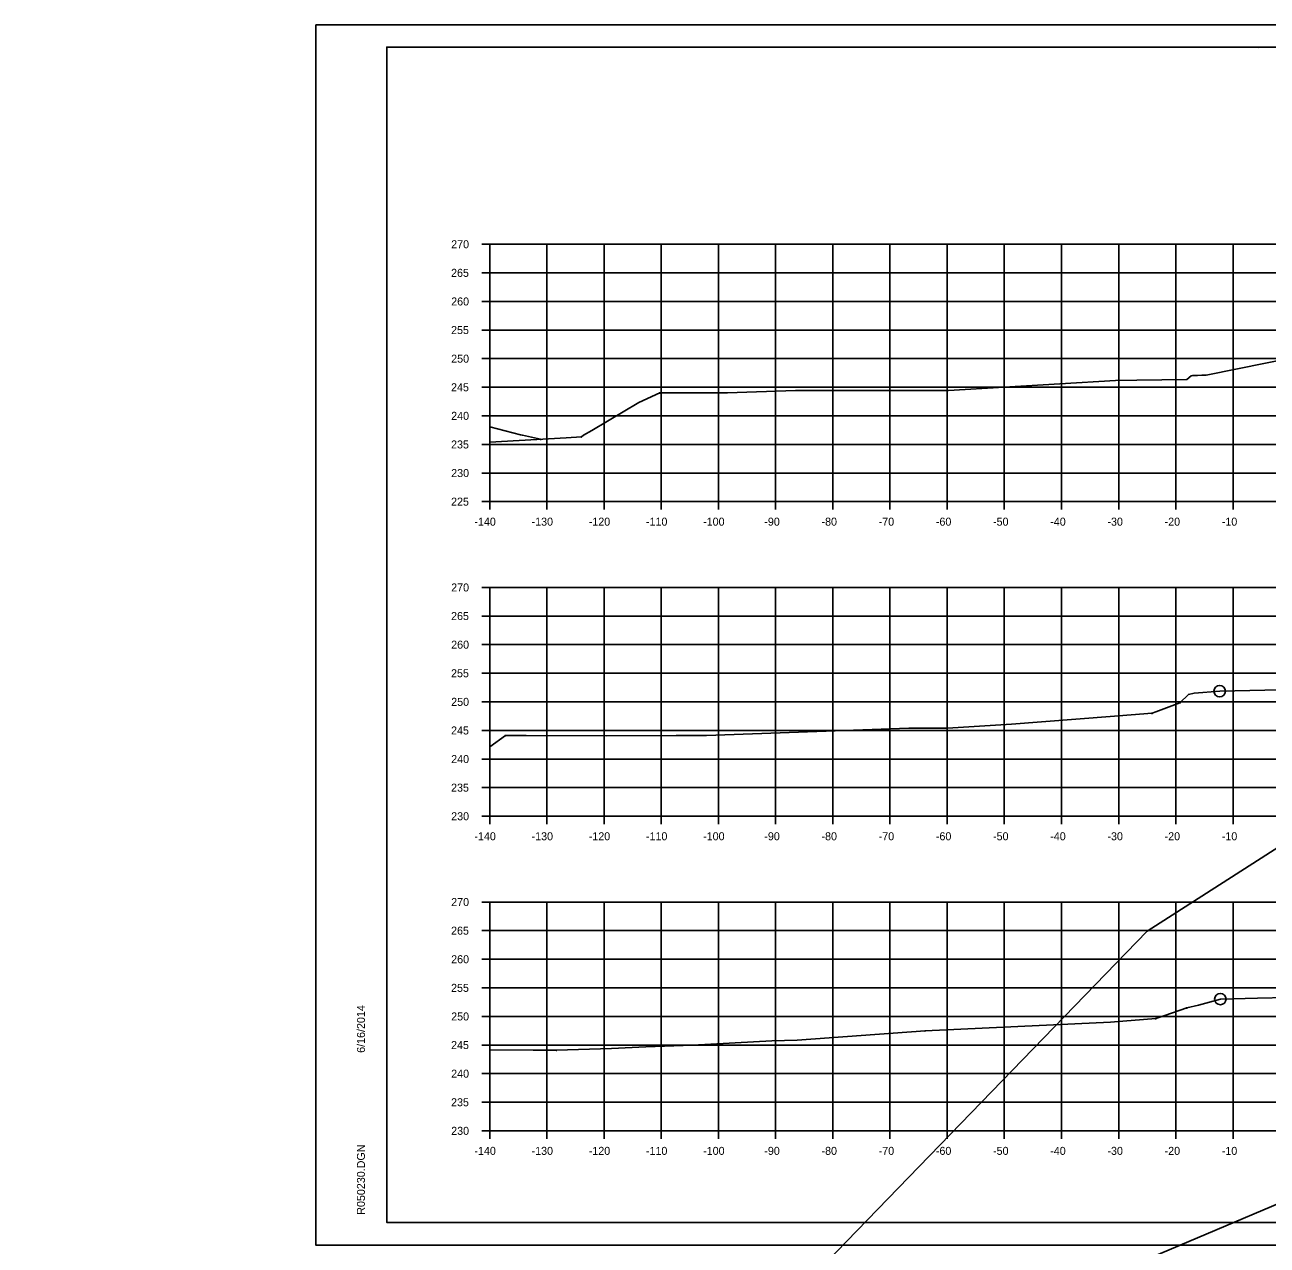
# Model space of a CAD drawing. Extents: x 1300404 to 1323571, y 234004 to 252077.
# Drawn here: x 1315496 to 1315713.2, y 240208.4 to 240421.8 of the extents above; entities that cross this region are included whole.
import ezdxf

# ---------------------------------------------------------------- set-up
doc = ezdxf.new("R2010")
doc.units = 0
for name, color, linetype in [('Default', 7, 'Continuous'), ('R_Axis', 7, 'Continuous'), ('R_Axis Annot', 7, 'Continuous'), ('R_Border', 7, 'Continuous'), ('R_Draft', 7, 'Continuous'), ('R_Exist Surface', 7, 'Continuous'), ('R_Fin Surface', 7, 'Continuous'), ('R_Floodway', 7, 'Continuous'), ('R_Flooplain', 7, 'Continuous'), ('R_Grid', 7, 'Continuous'), ('R_No Plot', 7, 'Continuous')]:
    doc.layers.add(name, color=color, linetype=linetype)

msp = doc.modelspace()

# ---------------------------------------------------------------- linework, layer by layer
at = {"layer": 'Default'}
for p, q in [((1315559.28, 240417.86), (1315875.46, 240417.86)), ((1315559.28, 240212.4), (1315559.28, 240417.86)), ((1315875.46, 240212.4), (1315559.28, 240212.4))]:
    msp.add_line(p, q, dxfattribs=at)
at = {"layer": 'R_Axis'}
for p, q in [((1315575.88, 240383.4), (1315577.28, 240383.4)), ((1315577.28, 240338.4), (1315577.28, 240383.4)), ((1315575.88, 240378.4), (1315577.28, 240378.4)), ((1315575.88, 240373.4), (1315577.28, 240373.4)), ((1315575.88, 240368.4), (1315577.28, 240368.4)), ((1315575.88, 240363.4), (1315577.28, 240363.4)), ((1315575.88, 240358.4), (1315577.28, 240358.4)), ((1315575.88, 240353.4), (1315577.28, 240353.4)), ((1315575.88, 240348.4), (1315577.28, 240348.4)), ((1315575.88, 240343.4), (1315577.28, 240343.4)), ((1315575.88, 240338.4), (1315577.28, 240338.4)), ((1315577.28, 240338.4), (1315857.28, 240338.4)), ((1315577.28, 240337), (1315577.28, 240338.4)), ((1315587.28, 240337), (1315587.28, 240338.4)), ((1315597.28, 240337), (1315597.28, 240338.4)), ((1315607.28, 240337), (1315607.28, 240338.4)), ((1315617.28, 240337), (1315617.28, 240338.4)), ((1315627.28, 240337), (1315627.28, 240338.4)), ((1315637.28, 240337), (1315637.28, 240338.4)), ((1315647.28, 240337), (1315647.28, 240338.4)), ((1315657.28, 240337), (1315657.28, 240338.4)), ((1315667.28, 240337), (1315667.28, 240338.4)), ((1315677.28, 240337), (1315677.28, 240338.4)), ((1315687.28, 240337), (1315687.28, 240338.4)), ((1315697.28, 240337), (1315697.28, 240338.4)), ((1315707.28, 240337), (1315707.28, 240338.4)), ((1315575.88, 240323.4), (1315577.28, 240323.4)), ((1315577.28, 240283.4), (1315577.28, 240323.4)), ((1315575.88, 240318.4), (1315577.28, 240318.4)), ((1315575.88, 240313.4), (1315577.28, 240313.4)), ((1315575.88, 240308.4), (1315577.28, 240308.4)), ((1315575.88, 240303.4), (1315577.28, 240303.4)), ((1315575.88, 240298.4), (1315577.28, 240298.4)), ((1315575.88, 240293.4), (1315577.28, 240293.4)), ((1315575.88, 240288.4), (1315577.28, 240288.4)), ((1315575.88, 240283.4), (1315577.28, 240283.4)), ((1315577.28, 240283.4), (1315857.28, 240283.4)), ((1315577.28, 240282), (1315577.28, 240283.4)), ((1315587.28, 240282), (1315587.28, 240283.4)), ((1315597.28, 240282), (1315597.28, 240283.4)), ((1315607.28, 240282), (1315607.28, 240283.4)), ((1315617.28, 240282), (1315617.28, 240283.4)), ((1315627.28, 240282), (1315627.28, 240283.4)), ((1315637.28, 240282), (1315637.28, 240283.4)), ((1315647.28, 240282), (1315647.28, 240283.4)), ((1315657.28, 240282), (1315657.28, 240283.4)), ((1315667.28, 240282), (1315667.28, 240283.4)), ((1315677.28, 240282), (1315677.28, 240283.4)), ((1315687.28, 240282), (1315687.28, 240283.4)), ((1315697.28, 240282), (1315697.28, 240283.4)), ((1315707.28, 240282), (1315707.28, 240283.4)), ((1315575.88, 240268.4), (1315577.28, 240268.4)), ((1315577.28, 240228.4), (1315577.28, 240268.4)), ((1315575.88, 240263.4), (1315577.28, 240263.4)), ((1315575.88, 240258.4), (1315577.28, 240258.4)), ((1315575.88, 240253.4), (1315577.28, 240253.4)), ((1315575.88, 240248.4), (1315577.28, 240248.4)), ((1315575.88, 240243.4), (1315577.28, 240243.4)), ((1315575.88, 240238.4), (1315577.28, 240238.4)), ((1315575.88, 240233.4), (1315577.28, 240233.4)), ((1315575.88, 240228.4), (1315577.28, 240228.4)), ((1315577.28, 240228.4), (1315857.28, 240228.4)), ((1315577.28, 240227), (1315577.28, 240228.4)), ((1315587.28, 240227), (1315587.28, 240228.4)), ((1315597.28, 240227), (1315597.28, 240228.4)), ((1315607.28, 240227), (1315607.28, 240228.4)), ((1315617.28, 240227), (1315617.28, 240228.4)), ((1315627.28, 240227), (1315627.28, 240228.4)), ((1315637.28, 240227), (1315637.28, 240228.4)), ((1315647.28, 240227), (1315647.28, 240228.4)), ((1315657.28, 240227), (1315657.28, 240228.4)), ((1315667.28, 240227), (1315667.28, 240228.4)), ((1315677.28, 240227), (1315677.28, 240228.4)), ((1315687.28, 240227), (1315687.28, 240228.4)), ((1315697.28, 240227), (1315697.28, 240228.4)), ((1315707.28, 240227), (1315707.28, 240228.4))]:
    msp.add_line(p, q, dxfattribs=at)
at = {"layer": 'R_Border'}
for p, q in [((1315711.8, 240417.6), (1315711.8, 240417.6)), ((1315711.8, 240417.6), (1315711.8, 240417.6)), ((1315559.28, 240212.4), (1315559.28, 240212.4))]:
    msp.add_line(p, q, dxfattribs=at)
at = {"layer": 'R_Draft'}
for points in [[(1315699.17, 240359.83), (1315699.22, 240359.73), (1315699.12, 240359.73)], [(1315607.02, 240357.47), (1315607.07, 240357.37), (1315606.97, 240357.37)], [(1315586.19, 240349.35), (1315586.24, 240349.25), (1315586.14, 240349.25)], [(1315586.19, 240349.35), (1315586.24, 240349.25), (1315586.14, 240349.25)], [(1315593.31, 240349.78), (1315593.36, 240349.68), (1315593.26, 240349.68)], [(1315697.99, 240303.3), (1315698.04, 240303.2), (1315697.94, 240303.2)], [(1315693.11, 240301.45), (1315693.16, 240301.35), (1315693.06, 240301.35)], [(1315580.05, 240297.58), (1315580.1, 240297.48), (1315580, 240297.48)], [(1315699.19, 240249.94), (1315699.24, 240249.84), (1315699.14, 240249.84)], [(1315693.75, 240248.07), (1315693.8, 240247.97), (1315693.7, 240247.97)], [(1315653.41, 240245.94), (1315653.46, 240245.84), (1315653.36, 240245.84)], [(1315588.95, 240242.57), (1315589, 240242.47), (1315588.9, 240242.47)]]:
    msp.add_lwpolyline(points, close=True, dxfattribs=at)
at = {"layer": 'R_Exist Surface'}
for points in [[(1315577.28, 240348.79), (1315590.67, 240349.54), (1315593.31, 240349.73), (1315593.67, 240350.01), (1315595.17, 240350.84), (1315603.37, 240355.73), (1315607.02, 240357.42), (1315618.86, 240357.42), (1315630.79, 240357.85), (1315646.67, 240357.82), (1315657.52, 240357.81), (1315686.75, 240359.59), (1315690.45, 240359.66), (1315699.17, 240359.78), (1315699.97, 240360.4), (1315700.02, 240360.4), (1315700.22, 240360.46), (1315700.27, 240360.46), (1315700.32, 240360.46), (1315700.46, 240360.46), (1315700.87, 240360.47), (1315701, 240360.47), (1315701.08, 240360.47), (1315701.83, 240360.5), (1315702.14, 240360.51), (1315702.58, 240360.52), (1315718.41, 240363.74)], [(1315577.28, 240295.56), (1315580.05, 240297.53), (1315581.67, 240297.52), (1315583.69, 240297.51), (1315597.75, 240297.46), (1315609.89, 240297.52), (1315615.18, 240297.52), (1315650.59, 240298.81), (1315654.59, 240298.8), (1315657.33, 240298.79), (1315668.52, 240299.48), (1315685.78, 240300.82), (1315693.11, 240301.4), (1315693.79, 240301.64), (1315697.99, 240303.25), (1315699.47, 240304.69), (1315700.48, 240304.94), (1315704.94, 240305.27), (1315712.85, 240305.44), (1315714.85, 240305.52)], [(1315577.28, 240242.56), (1315584.88, 240242.52), (1315588.95, 240242.52), (1315598.57, 240242.8), (1315604.59, 240243.09), (1315612.72, 240243.38), (1315626.65, 240244.12), (1315631.08, 240244.28), (1315653.41, 240245.89), (1315685.82, 240247.4), (1315693.75, 240248.02), (1315695.34, 240248.59), (1315699.19, 240249.89), (1315701.22, 240250.38), (1315705.06, 240251.44), (1315711.57, 240251.59), (1315716.75, 240251.7)]]:
    msp.add_lwpolyline(points, dxfattribs=at)
at = {"layer": 'R_Fin Surface'}
msp.add_lwpolyline([(1315577.28, 240351.45), (1315582.65, 240350.07), (1315582.97, 240350), (1315583.02, 240350), (1315586.19, 240349.3)], dxfattribs=at)
at = {"layer": 'R_Floodway'}
msp.add_lwpolyline([(1316837.8, 240552.77), (1316620.61, 240466.93), (1316398.83, 240386.16), (1316131.18, 240356.09), (1315994.58, 240333.94), (1315688.1, 240204.21), (1315576.62, 240103.36), (1315282.23, 239827.84), (1314935.72, 239477.52)], dxfattribs=at)
at = {"layer": 'R_Flooplain'}
for p, q in [((1315692.25, 240263.28), (1316007.17, 240465.17)), ((1314740.93, 239282.88), (1315692.25, 240263.28))]:
    msp.add_line(p, q, dxfattribs=at)
at = {"layer": 'R_Grid'}
for p, q in [((1315577.28, 240383.4), (1315857.28, 240383.4)), ((1315577.28, 240338.4), (1315577.28, 240383.4)), ((1315587.28, 240338.4), (1315587.28, 240383.4)), ((1315597.28, 240338.4), (1315597.28, 240383.4)), ((1315607.28, 240338.4), (1315607.28, 240383.4)), ((1315617.28, 240338.4), (1315617.28, 240383.4)), ((1315627.28, 240338.4), (1315627.28, 240383.4)), ((1315637.28, 240338.4), (1315637.28, 240383.4)), ((1315647.28, 240338.4), (1315647.28, 240383.4)), ((1315657.28, 240338.4), (1315657.28, 240383.4)), ((1315667.28, 240338.4), (1315667.28, 240383.4)), ((1315677.28, 240338.4), (1315677.28, 240383.4)), ((1315687.28, 240338.4), (1315687.28, 240383.4)), ((1315697.28, 240338.4), (1315697.28, 240383.4)), ((1315707.28, 240338.4), (1315707.28, 240383.4)), ((1315577.28, 240378.4), (1315857.28, 240378.4)), ((1315577.28, 240373.4), (1315857.28, 240373.4)), ((1315577.28, 240368.4), (1315857.28, 240368.4)), ((1315577.28, 240363.4), (1315857.28, 240363.4)), ((1315577.28, 240358.4), (1315857.28, 240358.4)), ((1315577.28, 240353.4), (1315857.28, 240353.4)), ((1315577.28, 240348.4), (1315857.28, 240348.4)), ((1315577.28, 240343.4), (1315857.28, 240343.4)), ((1315577.28, 240338.4), (1315857.28, 240338.4)), ((1315577.28, 240323.4), (1315857.28, 240323.4)), ((1315577.28, 240283.4), (1315577.28, 240323.4)), ((1315587.28, 240283.4), (1315587.28, 240323.4)), ((1315597.28, 240283.4), (1315597.28, 240323.4)), ((1315607.28, 240283.4), (1315607.28, 240323.4)), ((1315617.28, 240283.4), (1315617.28, 240323.4)), ((1315627.28, 240283.4), (1315627.28, 240323.4)), ((1315637.28, 240283.4), (1315637.28, 240323.4)), ((1315647.28, 240283.4), (1315647.28, 240323.4)), ((1315657.28, 240283.4), (1315657.28, 240323.4)), ((1315667.28, 240283.4), (1315667.28, 240323.4)), ((1315677.28, 240283.4), (1315677.28, 240323.4)), ((1315687.28, 240283.4), (1315687.28, 240323.4)), ((1315697.28, 240283.4), (1315697.28, 240323.4)), ((1315707.28, 240283.4), (1315707.28, 240323.4)), ((1315577.28, 240318.4), (1315857.28, 240318.4)), ((1315577.28, 240313.4), (1315857.28, 240313.4)), ((1315577.28, 240308.4), (1315857.28, 240308.4)), ((1315577.28, 240303.4), (1315857.28, 240303.4)), ((1315577.28, 240298.4), (1315857.28, 240298.4)), ((1315577.28, 240293.4), (1315857.28, 240293.4)), ((1315577.28, 240288.4), (1315857.28, 240288.4)), ((1315577.28, 240283.4), (1315857.28, 240283.4)), ((1315577.28, 240268.4), (1315857.28, 240268.4)), ((1315577.28, 240228.4), (1315577.28, 240268.4)), ((1315587.28, 240228.4), (1315587.28, 240268.4)), ((1315597.28, 240228.4), (1315597.28, 240268.4)), ((1315607.28, 240228.4), (1315607.28, 240268.4)), ((1315617.28, 240228.4), (1315617.28, 240268.4)), ((1315627.28, 240228.4), (1315627.28, 240268.4)), ((1315637.28, 240228.4), (1315637.28, 240268.4)), ((1315647.28, 240228.4), (1315647.28, 240268.4)), ((1315657.28, 240228.4), (1315657.28, 240268.4)), ((1315667.28, 240228.4), (1315667.28, 240268.4)), ((1315677.28, 240228.4), (1315677.28, 240268.4)), ((1315687.28, 240228.4), (1315687.28, 240268.4)), ((1315697.28, 240228.4), (1315697.28, 240268.4)), ((1315707.28, 240228.4), (1315707.28, 240268.4)), ((1315577.28, 240263.4), (1315857.28, 240263.4)), ((1315577.28, 240258.4), (1315857.28, 240258.4)), ((1315577.28, 240253.4), (1315857.28, 240253.4)), ((1315577.28, 240248.4), (1315857.28, 240248.4)), ((1315577.28, 240243.4), (1315857.28, 240243.4)), ((1315577.28, 240238.4), (1315857.28, 240238.4)), ((1315577.28, 240233.4), (1315857.28, 240233.4)), ((1315577.28, 240228.4), (1315857.28, 240228.4))]:
    msp.add_line(p, q, dxfattribs=at)
at = {"layer": 'R_No Plot'}
for p, q in [((1315546.87, 240421.76), (1315880.21, 240421.76)), ((1315546.87, 240208.42), (1315880.21, 240208.42))]:
    msp.add_line(p, q, dxfattribs=at)
for points in [[(1315546.87, 240421.76), (1315880.21, 240421.76), (1315880.21, 240208.42), (1315546.87, 240208.42)], [(1315793.2, 240417.86), (1315793.2, 240407.98), (1315828.93, 240407.98), (1315828.93, 240405.06), (1315852.13, 240405.06), (1315852.13, 240382.94), (1315875.46, 240382.94), (1315875.46, 240212.4), (1315559.28, 240212.4), (1315559.28, 240417.86)]]:
    msp.add_lwpolyline(points, close=True, dxfattribs=at)
for centre in [(1315704.94, 240305.27), (1315705.06, 240251.44)]:
    msp.add_circle(centre, 1, dxfattribs=at)

# ---------------------------------------------------------------- texts
at = {"layer": 'R_Axis'}
for p in [(1315577.28, 240338.4), (1315577.28, 240283.4), (1315577.28, 240228.4)]:
    msp.add_text('-', height=0.0001, dxfattribs=at).set_placement(p)
at = {"layer": 'R_Axis Annot'}
for s, p in [('270', (1315570.55, 240382.7)), ('265', (1315570.53, 240377.7)), ('260', (1315570.55, 240372.7)), ('255', (1315570.53, 240367.7)), ('250', (1315570.55, 240362.7)), ('245', (1315570.53, 240357.7)), ('240', (1315570.55, 240352.7)), ('235', (1315570.53, 240347.7)), ('230', (1315570.55, 240342.7)), ('225', (1315570.53, 240337.7)), ('-140', (1315574.61, 240334.2)), ('-130', (1315584.61, 240334.2)), ('-120', (1315594.61, 240334.2)), ('-110', (1315604.61, 240334.2)), ('-100', (1315614.61, 240334.2)), ('-90', (1315625.31, 240334.2)), ('-80', (1315635.31, 240334.2)), ('-70', (1315645.31, 240334.2)), ('-60', (1315655.31, 240334.2)), ('-50', (1315665.31, 240334.2)), ('-40', (1315675.31, 240334.2)), ('-30', (1315685.31, 240334.2)), ('-20', (1315695.31, 240334.2)), ('-10', (1315705.31, 240334.2)), ('270', (1315570.55, 240322.7)), ('265', (1315570.53, 240317.7)), ('260', (1315570.55, 240312.7)), ('255', (1315570.53, 240307.7)), ('250', (1315570.55, 240302.7)), ('245', (1315570.53, 240297.7)), ('240', (1315570.55, 240292.7)), ('235', (1315570.53, 240287.7)), ('230', (1315570.55, 240282.7)), ('-140', (1315574.61, 240279.2)), ('-130', (1315584.61, 240279.2)), ('-120', (1315594.61, 240279.2)), ('-110', (1315604.61, 240279.2)), ('-100', (1315614.61, 240279.2)), ('-90', (1315625.31, 240279.2)), ('-80', (1315635.31, 240279.2)), ('-70', (1315645.31, 240279.2)), ('-60', (1315655.31, 240279.2)), ('-50', (1315665.31, 240279.2)), ('-40', (1315675.31, 240279.2)), ('-30', (1315685.31, 240279.2)), ('-20', (1315695.31, 240279.2)), ('-10', (1315705.31, 240279.2)), ('270', (1315570.55, 240267.7)), ('265', (1315570.53, 240262.7)), ('260', (1315570.55, 240257.7)), ('255', (1315570.53, 240252.7)), ('250', (1315570.55, 240247.7)), ('245', (1315570.53, 240242.7)), ('240', (1315570.55, 240237.7)), ('235', (1315570.53, 240232.7)), ('230', (1315570.55, 240227.7)), ('-140', (1315574.61, 240224.2)), ('-130', (1315584.61, 240224.2)), ('-120', (1315594.61, 240224.2)), ('-110', (1315604.61, 240224.2)), ('-100', (1315614.61, 240224.2)), ('-90', (1315625.31, 240224.2)), ('-80', (1315635.31, 240224.2)), ('-70', (1315645.31, 240224.2)), ('-60', (1315655.31, 240224.2)), ('-50', (1315665.31, 240224.2)), ('-40', (1315675.31, 240224.2)), ('-30', (1315685.31, 240224.2)), ('-20', (1315695.31, 240224.2)), ('-10', (1315705.31, 240224.2))]:
    msp.add_text(s, height=1.4, dxfattribs=at).set_placement(p)
at = {"layer": 'R_Border'}
for s, p in [('6/16/2014', (1315555.47, 240242.04)), ('R050230.DGN', (1315555.47, 240213.73))]:
    msp.add_text(s, height=1.4, rotation=90, dxfattribs=at).set_placement(p)

doc.saveas('drawing.dxf')
